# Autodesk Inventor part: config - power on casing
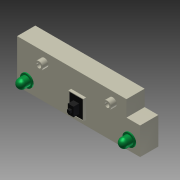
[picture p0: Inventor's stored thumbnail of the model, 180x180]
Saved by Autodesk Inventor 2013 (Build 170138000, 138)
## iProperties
Created: 2005-12
Part Number: config - power on casing
Document SubType Name: Modeling
Designer: Autodesk Inc.
Stock Number: config - power on casing
Density: 1 g/cm^3
Categories: <MemberInstance><Categories><Category DisplayName="" Mnemonic="CABLEANDHARNESS" InternalName="e4a7e005-5e42-4d16-b293-125e7f0d0512"><Category DisplayName="" Mne
Mass: 8.54104 g
Surface Area: 37.5676 cm^2
Volume: 8.54104 cm^3
Material: Allgemein
Company: Autodesk Inc.
GlobalPropertyList: <PropertyList/>
Title: PC Demo
Author: Autodesk Inc.
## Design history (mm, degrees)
sketch "Sketch2"
  geometry: L1 (0, -3.8)-(0, 22.8) reference; L2 (-37.8, 0)-(37.8, 0) reference; L3 (-27, 0)-(27, 0); L4 (27, 0)-(27, 12); L5 (27, 12)-(-27, 12); L6 (-27, 12)-(-27, 0); L7 (-21, 12)-(27, 12); L8 (27, 12)-(27, 19); L9 (27, 19)-(-21, 19); L10 (-21, 19)-(-21, 12); 1 further point
  constraints: 16 end point, 4 parallel, 2 horizontal, 2 perpendicular, 2 point on line, 1 collinear, 1 other
  dimensions: "d0" = 54 distance between parallel lines of L4 L6; "d1" = 12 distance of L3.end L4.end; "d2" = 7 distance of L7.end L8.end; "d3" = 48 distance of L8.end L9.end
extrude "Extrusion1" new body sketch "Sketch2" distance "d4" = 8; taper "d5" = 0 deg
sketch "Sketch4"
  geometry: L1 (-27, 0)-(27, 0) reference; L2 (0, 3.8)-(0, -22.8) reference; L3 (-7.5, 0)-(7.5, 0); L4 (7.5, 0)-(7.5, -8); L5 (7.5, -8)-(-7.5, -8); L6 (-7.5, -8)-(-7.5, 0)
  constraints: 8 end point, 2 parallel, 1 horizontal, 1 perpendicular, 1 point on line, 1 other
  dimensions: "d6" = 15 distance of L4.end L5.end; "d7" = 8 distance of L5.end L3.start
extrude "Extrusion2" join sketch "Sketch4" distance "d8" = 5; taper "d9" = 0 deg
sketch "Sketch5"
  geometry: L1 (27, 0)-(-27, 0) reference; L2 (0, 22.8)-(0, -3.8) reference; C1 r 1.75 at (-15, 15); C2 r 1.75 at (15, 15); C3 r 1 at (-15, 15); C4 r 1 at (15, 15)
  constraints: 4 centre point, 2 coincident, 2 equal radius, 1 horizontal alignment, 1 symmetric about line
  dimensions: "d10" = 30 distance of C2.centre C1.centre; "d11" = 3.5 diameter of C2; "d12" = 15 distance from line of L1 C1.centre; "d15" = 2 diameter of C3
extrude "Extrusion4" join sketch "Sketch5" distance "d16" = 2.5; taper "d17" = 0 deg
sketch "Sketch6"
  geometry: L1 (27, 0)-(-27, 0) reference; L2 (0, 22.8)-(0, -3.8) reference; L3 (-3, 10.5)-(3, 10.5); L4 (3, 10.5)-(3, 2.5); L5 (3, 2.5)-(-3, 2.5); L6 (-3, 2.5)-(-3, 10.5)
  constraints: 8 end point, 2 parallel, 1 horizontal, 1 perpendicular, 1 other
  dimensions: "d18" = 8 distance of L5.end L3.start; "d19" = 6 distance of L3.start L3.end; "d20" = 2.5 distance between parallel lines of L1 L5
extrude "Extrusion5" join sketch "Sketch6" distance "d21" = 1; taper "d22" = 0 deg
sketch "Sketch7"
  geometry: L1 (-3, 10.5)-(3, 10.5) reference; L2 (3, 2.5)-(-3, 2.5) reference; L3 (-1.25, 8)-(1.25, 8); L4 (1.25, 8)-(1.25, 4); L5 (1.25, 4)-(-1.25, 4); L6 (-1.25, 4)-(-1.25, 8); L7 (0, 22.8)-(0, -3.8) reference
  constraints: 8 end point, 2 parallel, 1 horizontal, 1 perpendicular, 1 other
  dimensions: "d23" = 4 distance of L3.end L4.end; "d24" = 2.5 distance of L3.start L3.end; "d25" = 2.5 distance between parallel lines of L3 L1; "d26" = 1.5 distance between parallel lines of L2 L5 (derived)
extrude "Extrusion6" join sketch "Sketch7" distance "d27" = 2.5; taper "d28" = 0 deg
sketch "Sketch8"
  geometry: L1 (1.25, 8)-(1.25, 4) reference; L2 (-1.25, 8)-(1.25, 8) reference; L3 (-1.25, 4)-(-1.25, 8) reference; L4 (1.25, 4)-(-1.25, 4) reference; L5 (0, 8)-(0, 4); L6 (-1.25, 6)-(1.25, 6); L7 (-0.6, 6.6)-(0.6, 6.6); L8 (0.6, 6.6)-(0.6, 5.4); L9 (0.6, 5.4)-(-0.6, 5.4); L10 (-0.6, 5.4)-(-0.6, 6.6)
  constraints: 12 end point, 4 midpoint, 2 parallel, 2 perpendicular, 1 horizontal, 2 other
  dimensions: "d29" = 1.2 distance of L7.start L7.end
extrude "Extrusion7" join sketch "Sketch8" distance "d30" = 1; taper "d31" = 0 deg
sketch "Sketch9"
  geometry: L1 (3, 10.5)-(3, 2.5) reference; L2 (3, 2.5)-(-3, 2.5) reference; L3 (-3, 2.5)-(-3, 10.5) reference; L4 (-3, 10.5)-(3, 10.5) reference; L5 (3.3, 10.8)-(3.3, 2.2); L6 (3.3, 2.2)-(-3.3, 2.2); L7 (-3.3, 2.2)-(-3.3, 10.8); L8 (-3.3, 10.8)-(3.3, 10.8)
  constraints: 8 end point, 3 other
  dimensions: "d32" = 0.3 distance between parallel lines of L4 L8
extrude "Extrusion8" join sketch "Sketch9" distance "d33" = 1.2; taper "d34" = 0 deg
sketch "Sketch10"
  geometry: L1 (27, 0)-(-27, 0) reference; L2 (0, 22.8)-(0, -3.8) reference; C1 r 2.75 at (-22.5, 4.5)
  constraints: 1 centre point
  dimensions: "d35" = 5.5 diameter of C1; "d36" = 22.5 distance from line of L2 C1.centre; "d37" = 4.5 distance from line of L1 C1.centre
extrude "Extrusion9" join sketch "Sketch10" distance "d38" = 0.5; taper "d39" = 0 deg
sketch "Sketch11"
  geometry: C1 r 2.75 at (0, 0) reference; C2 r 2 at (0, 0)
  constraints: 1 centre point, 1 coincident
  dimensions: "d40" = 4 diameter of C2
extrude "Extrusion10" join sketch "Sketch11" distance "d41" = 4; taper "d42" = 0 deg
fillet "Fillet1" dims "d43" = 2
mirror "Mirror1"
sketch "Sketch12"
  geometry: L1 (-7.5, 0)-(7.5, 0) reference; L2 (-4, -1.5)-(4, -1.5); L3 (4, -1.5)-(4, -4.5); L4 (4, -4.5)-(-4, -4.5); L5 (-4, -4.5)-(-4, -1.5); L6 (-6, -4.5)-(6, -4.5); L7 (6, -4.5)-(6, -6.5); L8 (6, -6.5)-(-6, -6.5); L9 (-6, -6.5)-(-6, -4.5); L10 (0, 3.8)-(0, -22.8) reference
  constraints: 16 end point, 4 parallel, 2 horizontal, 2 perpendicular, 1 point on line, 2 other
  dimensions: "d44" = 3 distance of L4.end L2.start; "d45" = 2 distance of L8.end L6.start; "d46" = 12 distance of L7.end L8.end; "d47" = 8 distance of L2.start L2.end; "d48" = 1.5 distance between parallel lines of L2 L1
extrude "Extrusion11" cut sketch "Sketch12" distance "d49" = 2; taper "d50" = 0 deg
sketch "Sketch13" dims "d51" = 4
  geometry: L1 (-27, 0)-(-7.5, 0) reference; L2 (0, 3.8)-(0, -22.8) reference; L3 (-20.75, -1.25)-(-19.25, -1.25); L4 (-19.25, -1.25)-(-19.25, -6.75); L5 (-19.25, -6.75)-(-20.75, -6.75); L6 (-20.75, -6.75)-(-20.75, -1.25); L7 (-20, -4)-(-20, -1.25); L8 (-20, -4)-(-18, -4)
  constraints: 12 end point, 2 parallel, 2 perpendicular, 1 horizontal, 1 horizontal alignment, 1 midpoint, 1 vertical, 3 other
  dimensions: "d52" = 5.5 distance of L5.end L3.start; "d53" = 1.5 distance of L3.start L3.end; "d54" = 20 distance from line of L2 L7.start; "d55" = 4 distance from line of L7.start L1
extrude "Extrusion12" cut sketch "Sketch13" distance "d56" = 2; taper "d57" = 0 deg
mirror "Mirror2"
sketch "Sketch14"
  geometry: L1 (-6, -4.5)-(-6, -6.5) reference; L2 (-6, -6.5)-(6, -6.5) reference; L3 (6, -6.5)-(6, -4.5) reference; L4 (6, -4.5)-(4, -4.5) reference; L5 (4, -4.5)-(4, -1.5) reference; L6 (4, -1.5)-(-4, -1.5) reference; L7 (-4, -1.5)-(-4, -4.5) reference; L8 (-4, -4.5)-(-6, -4.5) reference; L9 (0, 3.8)-(0, -22.8) reference; 3 further points
  constraints: 1 point on line, 1 symmetric about line
sketch "Sketch15"
  geometry: L1 (-20.75, -1.25)-(-20.75, -2.146) reference; L2 (-20.75, -5.854)-(-20.75, -6.75) reference; L3 (-20.75, -6.75)-(-19.25, -6.75) reference; L4 (-19.25, -6.75)-(-19.25, -5.854) reference; L5 (-19.25, -2.146)-(-19.25, -1.25) reference; L6 (-19.25, -1.25)-(-20.75, -1.25) reference; L7 (-20, -4)-(-20, -5.289); L8 (20, -4)-(20, -5.584); A1 r 2 centre (-20, -4) between (-20.75, -2.146) and (-20.75, -5.854) reference; A2 r 2 centre (-20, -4) between (-19.25, -5.854) and (-19.25, -2.146) reference; A3 r 2 centre (20, -4) between (19.25, -2.146) and (19.25, -5.854) reference; 4 further points
  constraints: 4 end point, 2 symmetric about line, 1 parallel, 1 perpendicular
node "1"
node "2"
node "3"
node "4"
node "5"
node "6"
workpoint "Work Point7"
workpoint "Work Point8"
workpoint "Work Point9"
workpoint "Work Point10"
workpoint "Work Point11"
body "Solid1"
